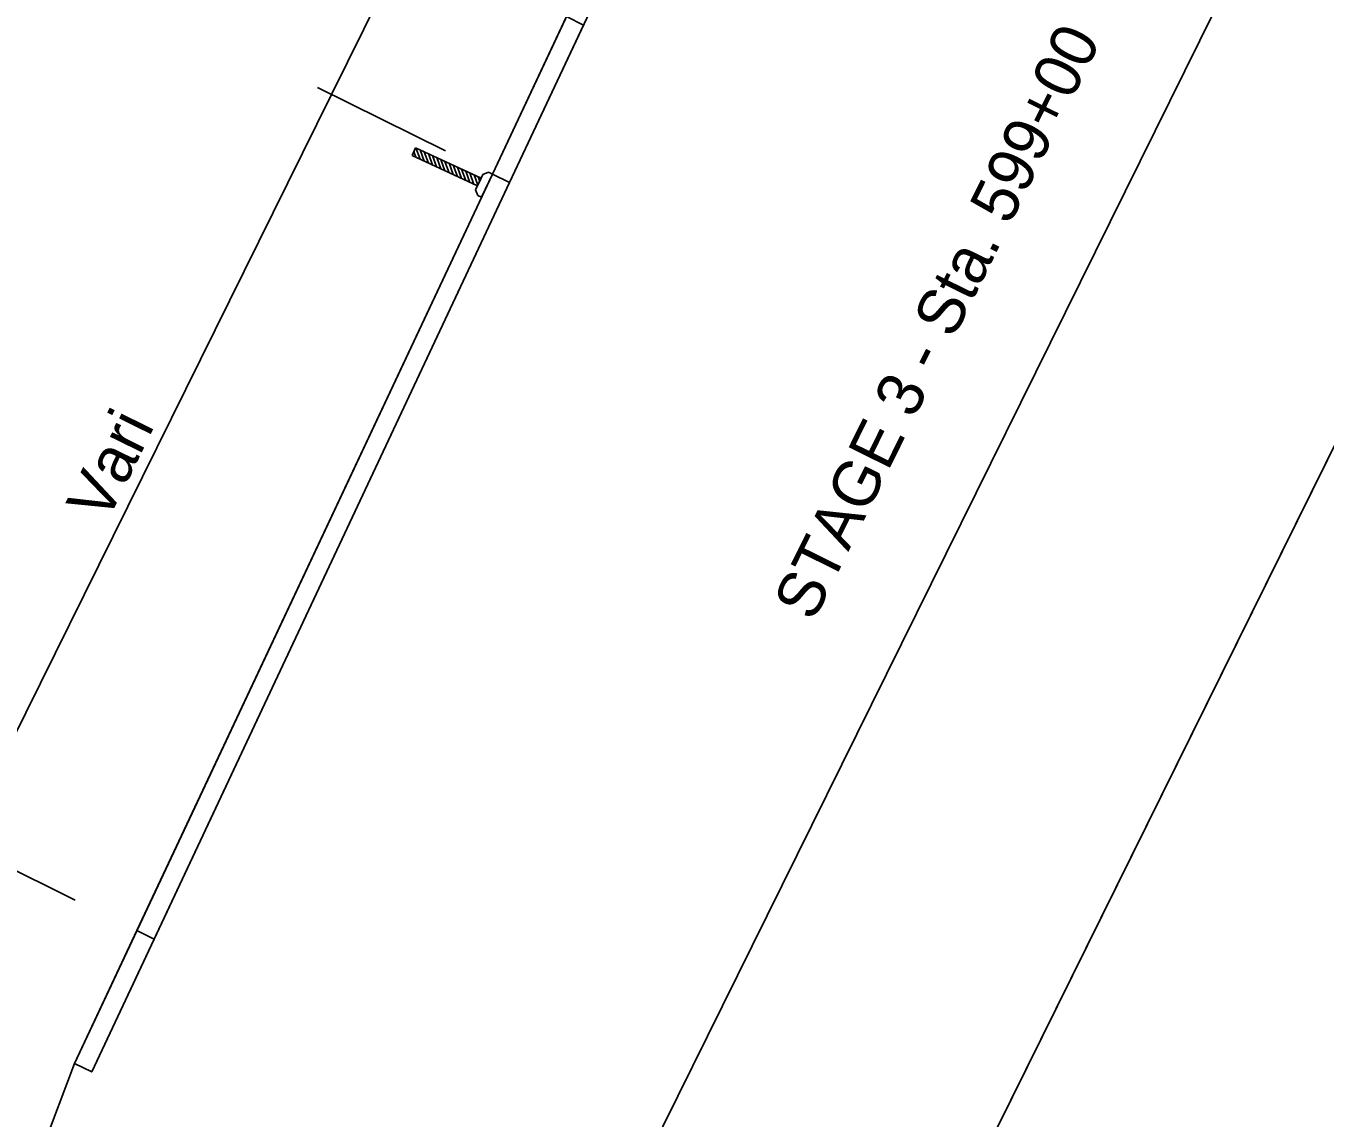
# Model space of a CAD drawing. Extents: x 14104283 to 14128447, y 8633203 to 8671666.
# Drawn here: x 14118152.7 to 14118377.8, y 8668318.4 to 8668507.7 of the extents above; entities that cross this region are included whole.
import ezdxf

# ---------------------------------------------------------------- set-up
doc = ezdxf.new("R2010")
doc.units = 0
for name, color, linetype in [('Cell', 7, 'Continuous'), ('Default', 7, 'Continuous'), ('dsnNonPlotable', 7, 'Continuous'), ('dsnStgShadingPrevPav', 7, 'Continuous'), ('dsnTextFinalPlan', 7, 'Continuous'), ('dsnTextOverlapEven', 7, 'Continuous'), ('TC_SubstrataExistingPavement', 7, 'Continuous'), ('Terrain', 7, 'Continuous')]:
    doc.layers.add(name, color=color, linetype=linetype)

msp = doc.modelspace()

# ---------------------------------------------------------------- linework, layer by layer
at = {"layer": 'Cell'}
for p, q in [((14118219.58, 8668485.3), (14118220.21, 8668486.64)), ((14118220.26, 8668484.99), (14118219.9, 8668485.98)), ((14118220.21, 8668486.64), (14118231.55, 8668481.35)), ((14118220.98, 8668484.65), (14118220.26, 8668486.62)), ((14118221.7, 8668484.31), (14118220.98, 8668486.29)), ((14118222.42, 8668483.98), (14118221.7, 8668485.95)), ((14118223.13, 8668483.64), (14118222.42, 8668485.61)), ((14118219.58, 8668485.3), (14118230.92, 8668480.01)), ((14118223.85, 8668483.31), (14118223.14, 8668485.28)), ((14118224.57, 8668482.97), (14118223.86, 8668484.94)), ((14118225.29, 8668482.64), (14118224.57, 8668484.61)), ((14118226.01, 8668482.3), (14118225.29, 8668484.27)), ((14118226.73, 8668481.97), (14118226.01, 8668483.94)), ((14118227.45, 8668481.63), (14118226.73, 8668483.6)), ((14118228.17, 8668481.29), (14118227.45, 8668483.27)), ((14118228.89, 8668480.96), (14118228.17, 8668482.93)), ((14118229.6, 8668480.62), (14118228.89, 8668482.59)), ((14118230.32, 8668480.29), (14118229.61, 8668482.26)), ((14118230.98, 8668480.13), (14118230.33, 8668481.92)), ((14118230.61, 8668479.34), (14118231.87, 8668482.02)), ((14118231.55, 8668481.35), (14118230.92, 8668480.01)), ((14118231.31, 8668480.84), (14118231.04, 8668481.59)), ((14118231.87, 8668482.02), (14118231.55, 8668481.35)), ((14118231.63, 8668478.04), (14118233.51, 8668482.07)), ((14118231.63, 8668478.04), (14118233.51, 8668482.07)), ((14118232.85, 8668482.38), (14118231.87, 8668482.02)), ((14118231.87, 8668482.02), (14118232.85, 8668482.38)), ((14118233.51, 8668482.07), (14118232.85, 8668482.38)), ((14118232.85, 8668482.38), (14118233.51, 8668482.07)), ((14118230.92, 8668480.01), (14118230.61, 8668479.34)), ((14118230.61, 8668479.34), (14118230.96, 8668478.35)), ((14118230.61, 8668479.34), (14118230.96, 8668478.35)), ((14118230.96, 8668478.35), (14118231.63, 8668478.04)), ((14118230.96, 8668478.35), (14118231.63, 8668478.04))]:
    msp.add_line(p, q, dxfattribs=at)
at = {"layer": 'Default'}
msp.add_lwpolyline([(14118174.89, 8668349.44), (14118236.5, 8668480.6), (14118249.33, 8668507.9), (14118246.34, 8668509.38), (14118233.51, 8668482.07), (14118171.9, 8668350.92)], close=True, dxfattribs=at)
at = {"layer": 'dsnNonPlotable'}
msp.add_lwpolyline([(14118092.03, 8667853.71), (14118786.76, 8669258.84), (14119692.14, 8668811.2), (14118997.41, 8667406.07)], close=True, dxfattribs=at)
at = {"layer": 'dsnStgShadingPrevPav'}
msp.add_lwpolyline([(14118161.08, 8668327.89), (14118171.9, 8668350.92), (14118174.89, 8668349.44), (14118164.07, 8668326.41)], close=True, dxfattribs=at)
at = {"layer": 'dsnTextFinalPlan'}
for p, q in [((14118205.63, 8668495.86), (14118226.9, 8668538.89)), ((14118203.17, 8668497.07), (14118225.4, 8668486.08)), ((14118141.41, 8668365.99), (14118205.63, 8668495.86)), ((14118138.96, 8668367.2), (14118161.19, 8668356.21))]:
    msp.add_line(p, q, dxfattribs=at)
for points in [[(14117870.36, 8667977.42), (14118384.92, 8669018.16), (14118565.56, 8668928.85), (14118050.99, 8667888.12)], [(14118092.03, 8667853.71), (14118606.59, 8668894.44), (14118787.23, 8668805.14), (14118272.66, 8667764.4)]]:
    msp.add_lwpolyline(points, close=True, dxfattribs=at)
at = {"layer": 'dsnTextOverlapEven'}
msp.add_lwpolyline([(14117870.36, 8667977.42), (14118384.92, 8669018.16), (14118565.56, 8668928.85), (14118050.99, 8667888.12)], close=True, dxfattribs=at)
at = {"layer": 'TC_SubstrataExistingPavement'}
for p, q in [((14118164.07, 8668326.41), (14118236.5, 8668480.6)), ((14118171.9, 8668350.92), (14118174.89, 8668349.44)), ((14118161.08, 8668327.89), (14118164.07, 8668326.41))]:
    msp.add_line(p, q, dxfattribs=at)
msp.add_lwpolyline([(14118289.97, 8668602.25), (14118292.96, 8668600.77), (14118236.5, 8668480.6), (14118233.51, 8668482.07)], dxfattribs=at)
at = {"layer": 'Terrain'}
for p, q in [((14118233.51, 8668482.07), (14118289.97, 8668602.25)), ((14118161.08, 8668327.89), (14118233.51, 8668482.07)), ((14118161.08, 8668327.89), (14118155.41, 8668312.82))]:
    msp.add_line(p, q, dxfattribs=at)

# ---------------------------------------------------------------- texts
at = {"layer": 'dsnTextFinalPlan'}
for s, p in [('STAGE 3 - Sta. 599+00', (14118289.14, 8668404.27)), ('Vari', (14118166.61, 8668421.42))]:
    msp.add_text(s, height=8, rotation=63.6911, dxfattribs=at).set_placement(p)

doc.saveas('drawing.dxf')
